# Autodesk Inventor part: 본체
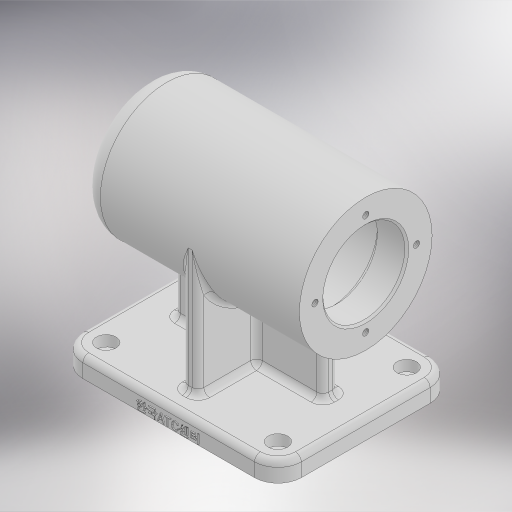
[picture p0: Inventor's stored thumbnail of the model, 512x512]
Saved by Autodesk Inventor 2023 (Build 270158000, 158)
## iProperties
Created: 2026-08
Part Number: 본체
Material: 일반
Document SubType Name: Modeling
Designer: home
Density: 1 g/cm^3
Appearance: 기본값
Mass: 379.96 g
Surface Area: 757.812 cm^2
Volume: 379.96 cm^3
Author: home
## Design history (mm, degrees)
sketch "스케치5"
  geometry: C1 r 34 at (0, 0); 1 further point
  constraints: 1 centre point, 1 coincident
  dimensions: "d28" = 68 diameter of C1
extrude "돌출1" new body sketch "스케치5" stored distance "d29" = 112; taper "d30" = 0 deg
sketch "스케치6"
  geometry: C1 r 21 at (0, 0); 1 further point
  constraints: 1 centre point, 1 coincident
  dimensions: "d31" = 42 diameter of C1
extrude "돌출2" cut sketch "스케치6" distance "d32" = 15; taper "d33" = 0 deg
sketch "스케치7"
  geometry: C1 r 24 at (0, 0); 1 further point
  constraints: 1 centre point, 1 coincident
  dimensions: "d34" = 48 diameter of C1
extrude "돌출3" cut sketch "스케치7" distance "d35" = 54; taper "d36" = 0 deg
sketch "스케치8"
  geometry: C1 r 21 at (0, 0); 1 further point
  constraints: 1 centre point, 1 coincident
  dimensions: "d37" = 42 diameter of C1
extrude "돌출4" cut sketch "스케치8" distance "d38" = 12; taper "d39" = 0 deg
sketch "스케치9"
  geometry: C1 r 17.5 at (0, 0); 1 further point
  constraints: 1 centre point, 1 coincident
  dimensions: "d40" = 35 diameter of C1
extrude "돌출5" cut sketch "스케치9" distance "d41" = 18; taper "d42" = 0 deg
sketch "스케치10"
  geometry: C1 r 16 at (0, 0); 1 further point
  constraints: 1 centre point, 1 coincident
  dimensions: "d43" = 32 diameter of C1
extrude "돌출6" cut sketch "스케치10" distance "d44" = 4; taper "d45" = 0 deg
sketch "스케치11"
  geometry: C1 r 10.5 at (0, 0); 1 further point
  constraints: 1 centre point, 1 coincident
  dimensions: "d46" = 21 diameter of C1
extrude "돌출7" cut sketch "스케치11" distance "d47" = 3; taper "d48" = 0 deg
fillet "모깎기1" dims "d49" = 3
fillet "모깎기2" dims "d50" = 0.6
fillet "모깎기3" dims "d51" = 0.6
fillet "모깎기4" dims "d52" = 3
fillet "모깎기5" dims "d53" = 3
chamfer "모따기1" distance "d54" = 1; stored, may be unused: second distance "d55" = 2, angle "d56" = 45 deg
fillet "모깎기6" dims "d57" = 10
sketch "스케치12"
  geometry: 2 further points
  constraints: 1 vertical alignment
  dimensions: "d65" = 26 distance of point (0, 0) point (0, 26)
hole "구멍1" sketch "스케치12" at (0, 26) diameter "d58" = 3.242; stored, may be unused: countersink angle "d62" = 90 deg, drill point angle "d64" = 118 deg; dims "d59" = 8, "d60" = 4, "d61" = 2, "d63" = 10
node "작업 평면1"
sketch "스케치13"
  geometry: L1 (56, -45)-(-56, -45); L2 (-56, -45)-(-56, 45); L3 (-56, 45)-(56, 45); L4 (56, 45)-(56, -45); 3 further points
  constraints: 8 end point, 2 midpoint, 2 parallel, 1 horizontal, 1 horizontal alignment, 1 perpendicular, 1 vertical alignment
  dimensions: "d70" = 90 distance of L1.end L2.end; "d71" = 112 distance of L2.end L3.end
extrude "돌출8" join sketch "스케치13" distance "d72" = 10; taper "d73" = 0 deg
fillet "모깎기7" dims "d74" = 12
sketch "스케치14"
  geometry: A1 r 12 centre (44, -33) between (44, -45) and (56, -33) reference; A2 r 12 centre (44, 33) between (56, 33) and (44, 45) reference; A3 r 12 centre (-44, -33) between (-56, -33) and (-44, -45) reference; A4 r 12 centre (-44, 33) between (-44, 45) and (-56, 33) reference; 5 further points
  constraints: 4 coincident
hole "구멍2" sketch "스케치14" at (44, -33), (44, 33), (-44, -33), (-44, 33) diameter "d75" = 5.5; stored, may be unused: countersink angle "d79" = 90 deg, drill point angle "d81" = 0 deg; dims "d76" = 8, "d77" = 10, "d78" = 5.5, "d80" = 10
sketch "스케치15"
  geometry: L1 (-38, 4)-(38, 4); L2 (38, 4)-(38, -4); L3 (38, -4)-(-38, -4); L4 (-38, -4)-(-38, 4); L5 (-4, 34)-(4, 34); L6 (4, 34)-(4, -34); L7 (4, -34)-(-4, -34); L8 (-4, -34)-(-4, 34); C1 r 2.75 at (44, 33) reference; C2 r 2.75 at (44, -33) reference; 9 further points
  constraints: 16 end point, 4 midpoint, 4 parallel, 2 horizontal, 2 horizontal alignment, 2 perpendicular, 2 vertical alignment
  dimensions: "d82" = 8 distance between parallel lines of L3 L1; "d83" = 76 distance of L1.start L1.end; "d84" = 68 distance of L7.end L5.start; "d85" = 8 distance of L5.start L5.end
extrude "돌출9" join sketch "스케치15" stored distance "d86" = 10; taper "d87" = 0 deg
fillet "모깎기8" dims "d88" = 3
sketch "스케치16"
  geometry: L1 (0, 0)-(88, 0) reference; 2 further points
  constraints: 1 vertical alignment, 1 other
  dimensions: "d89" = 3 distance from line of L1 point (44, 3)
fillet "모깎기9" dims "d90" = 3
fillet "모깎기10" dims "d91" = 3
fillet "모깎기11" dims "d92" = 3
fillet "모깎기12" dims "d93" = 3
feature "엠보싱1" dims "d94" = 0.5, "d95" = 0
feature "ͻ耀ͽ耀Ϳ耀΁耀΃耀΅耀·耀Ή耀" dims "d28" = 68, "d29" = 112, "d30" = 0, "d31" = 42, "d32" = 15, "d33" = 0, "d34" = 48, "d35" = 54, "d36" = 0, "d37" = 42, "d38" = 12, "d39" = 0, "d40" = 35, "d41" = 18, "d42" = 0, "d43" = 32, "d44" = 4, "d45" = 0, "d46" = 21, "d47" = 3, "d48" = 0, "d49" = 3, "d50" = 0.6, "d51" = 0.6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
node "솔리드1"
pattern_circular "원형 패턴1" dims angle "d67" = 360 deg
feature "A9D066F2-1C7D-4E18-AEED-F7BC21143FA4" dims "d58" = 3.242, "d59" = 8, "d60" = 4, "d61" = 2, "d62" = 90 deg, "d63" = 10, "d64" = 118 deg
